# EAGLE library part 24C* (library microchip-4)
Serial EEPROM 1 K/2 K/4 K
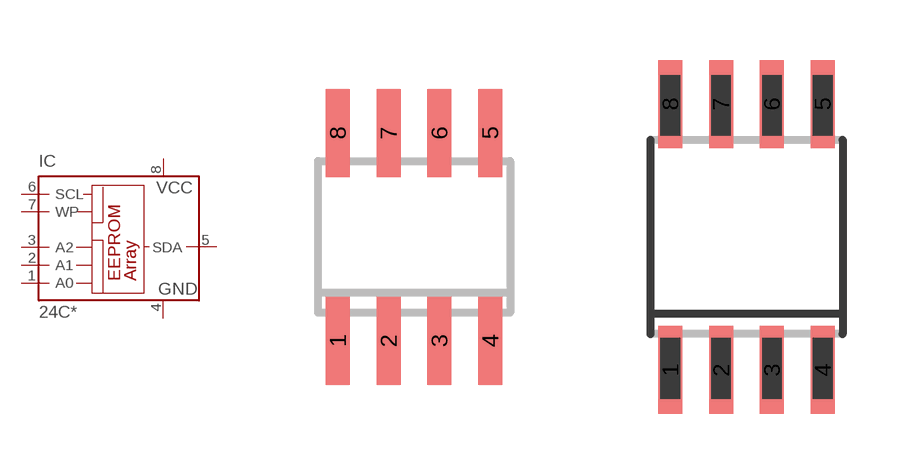
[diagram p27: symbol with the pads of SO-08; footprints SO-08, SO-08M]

Designator prefix IC

## 24C01SN, 24C01ASN, 24C01CSN, 24C02SN, 24C02ASN, 24C02CSN, 24C04SN, 24C04ASN, 24C04CSN  [SO-08]
1  A0  in
2  A1  in
3  A2  in
4  GND  pwr
5  SDA
6  SCL  in
7  WP  in
8  VCC  pwr

## 24C01SM, 24C01ASM, 24C01CSM, 24C02SM, 24C02ASM, 24C02CSM, 24C04SM, 24C04ASM  [SO-08M]
Pads as for SO-08

## 24C01P, 24C01AP, 24C01CP, 24C02P, 24C02AP, 24C02CP, 24C04P, 24C04AP, 24C04CP  [DIL8]
Pads as for SO-08

## 24C01SL, 24C02SL, 24C04SL  [SO-14]
2  A0  in
3  A1  in
5  A2  in
6  GND  pwr
9  SDA
10  SCL  in
12  WP  in
13  VCC  pwr

## Footprint SO-08 (pad centres in mm)
Small Outline Narrow Plastic Gull Wing 150-mil body, package type SN
smd 0.6 x 2.2: 1 -1.905,-2.6; 2 -0.635,-2.6; 3 0.635,-2.6; 4 1.905,-2.6; 5 1.905,2.6; 6 0.635,2.6; 7 -0.635,2.6; 8 -1.905,2.6

## Footprint SO-08M (pad centres in mm)
Small Outline Medium Plastic Gull Wing 207-mil body, package type SM
smd 0.6 x 2.2: 1 -1.905,-3.33; 2 -0.635,-3.33; 3 0.635,-3.33; 4 1.905,-3.33; 5 1.905,3.33; 6 0.635,3.33; 7 -0.635,3.33; 8 -1.905,3.33

## Footprint DIL8 (pad centres in mm)
Dual In Line package type P
drill 0.813 long: 1 -3.81,-3.81; 2 -1.27,-3.81; 3 1.27,-3.81; 4 3.81,-3.81; 5 3.81,3.81; 6 1.27,3.81; 7 -1.27,3.81; 8 -3.81,3.81

## Footprint SO-14 (pad centres in mm)
Small Outline Narrow Plastic Gull Wing 150-mil body, package type SL
smd 0.6 x 2.2: 1 -3.81,-2.6; 2 -2.54,-2.6; 3 -1.27,-2.6; 4 0,-2.6; 5 1.27,-2.6; 6 2.54,-2.6; 7 3.81,-2.6; 8 3.81,2.6; 9 2.54,2.6; 10 1.27,2.6; 11 0,2.6; 12 -1.27,2.6; 13 -2.54,2.6; 14 -3.81,2.6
